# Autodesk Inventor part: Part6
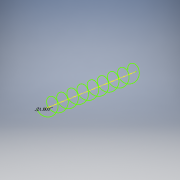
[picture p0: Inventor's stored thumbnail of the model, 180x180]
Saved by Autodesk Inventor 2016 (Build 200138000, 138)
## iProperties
Created: 2020-04
Part Number: Part6
Material: Generic
Document SubType Name: Modeling
Designer: merlin
Density: 1 g/cm^3
Appearance: Default
Author: merlin
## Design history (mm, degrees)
sketch "3D Sketch1"
  node "Helical Curve1" dims "d0" = 25.4, "d1" = 89.34, "d2" = 25.4, "d3" = 0
